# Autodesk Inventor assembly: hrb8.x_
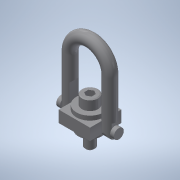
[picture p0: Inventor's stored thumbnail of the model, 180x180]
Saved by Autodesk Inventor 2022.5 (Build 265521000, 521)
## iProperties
Part Number: hrb8.x_
Material: 一般
Document SubType Name: Assembly
Designer: ImaoCorp
Sending System: SOLIDWORKS 2017-2017317
MC: AMD64
MC_MODEL: Intel64 Family 6 Model 60 Stepping 3, GenuineIntel
OS: Windows_NT
FRU: Parasolid Version 29.0, build 201,  4-17-2017
FORMAT: text
GUISE: transmit
KEY: hrb8
FILE: hrb8.x_t
DATE: Mon Jul 01 17:39:19 2019
Author: ImaoCorp
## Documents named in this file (3)
- X:\14_SW2022-Inv2022\00_全2023-1023新製品(TCC)まで\h\hrb8\HRB8.iam
- X:\14_SW2022-Inv2022\00_全2023-1023新製品(TCC)まで\h\hrb8\hrb8_01.ipt
- X:\14_SW2022-Inv2022\00_全2023-1023新製品(TCC)まで\h\hrb8\hrb8_02.ipt
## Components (2 placed, 2 different names)
1. hrb8_01
2. hrb8_02
